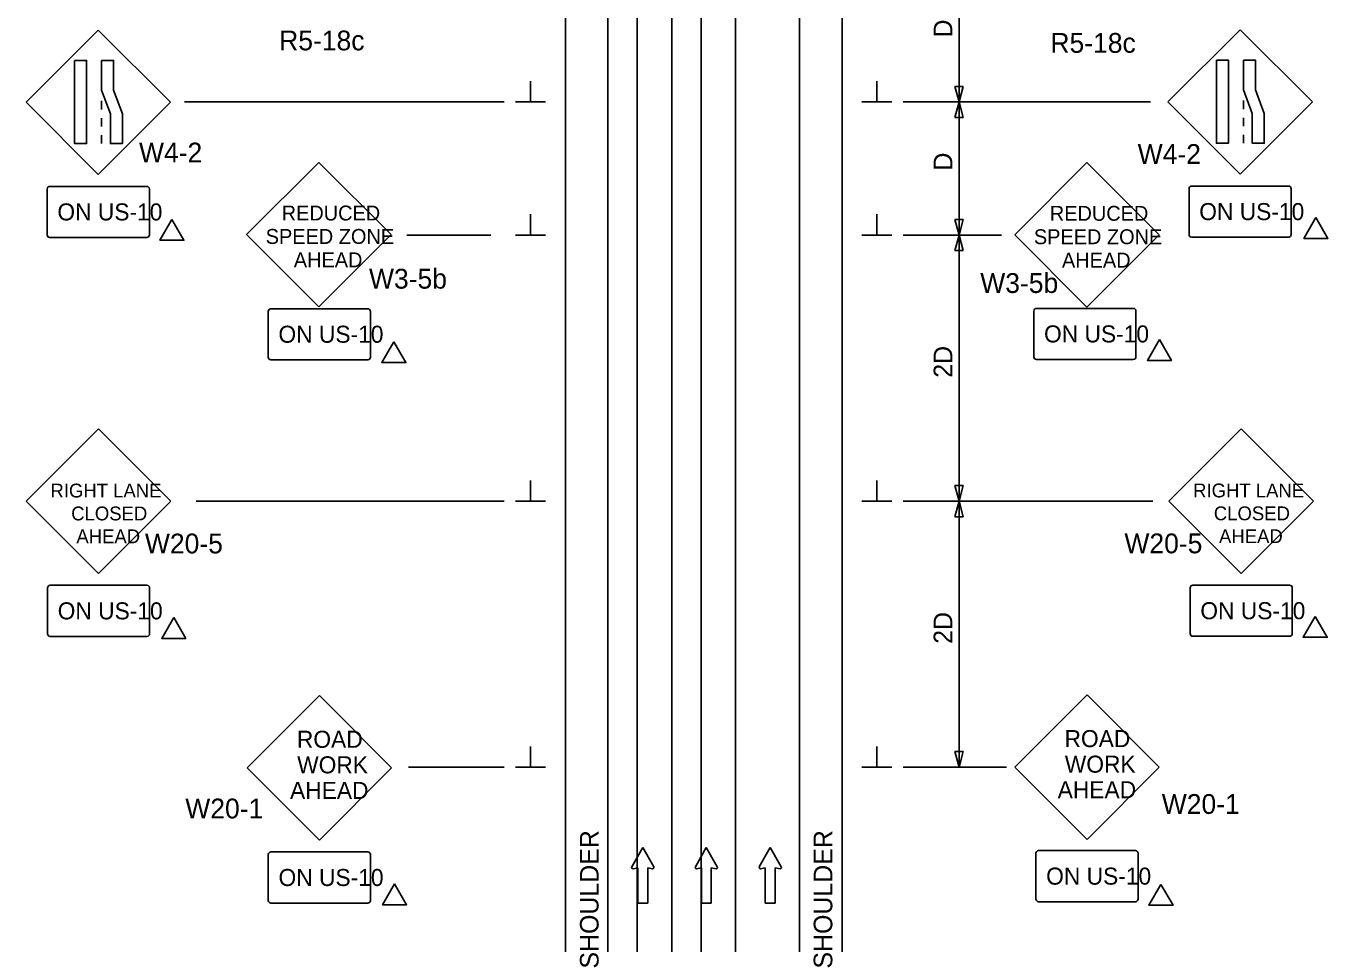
# Model space of a CAD drawing. Extents: x 16303 to 18479, y 5704 to 6974.
# Drawn here: x 16750.9 to 17240.3, y 6152.9 to 6497.9 of the extents above; entities that cross this region are included whole.
import ezdxf

# ---------------------------------------------------------------- set-up
doc = ezdxf.new("R2010")
doc.units = 0
for name, color, linetype in [('ALI_LEGAL_EX', 7, 'Continuous'), ('MT_SCRATCH_LEVEL_E', 7, 'Continuous'), ('PAVT_EDGE_EX', 7, 'Continuous'), ('TRAFFIC_SIGNS_PR', 7, 'Continuous'), ('TYPICAL_TEXT_DIMEN_PR', 7, 'Continuous')]:
    doc.layers.add(name, color=color, linetype=linetype)

msp = doc.modelspace()

# ---------------------------------------------------------------- linework, layer by layer
at = {"layer": 'ALI_LEGAL_EX'}
for p, q in [((16980.68, 6974.12), (16980.68, 6155.98)), ((17004.68, 6974.12), (17004.68, 6155.98)), ((16980.68, 6877.04), (16980.68, 6013.12)), ((17004.68, 6877.04), (17004.68, 6013.12)), ((16993.65, 6024.8), (16993.65, 6525.15)), ((17017.65, 6024.8), (17017.65, 6525.15))]:
    msp.add_line(p, q, dxfattribs=at)
for points in [[(16993.65, 6424.8), (16993.65, 6449.8)], [(17017.65, 6424.8), (17017.65, 6449.8)], [(16993.65, 6324.8), (16993.65, 6349.8)], [(17017.65, 6324.8), (17017.65, 6349.8)], [(16993.65, 6224.8), (16993.65, 6249.8)], [(17017.65, 6224.8), (17017.65, 6249.8)]]:
    msp.add_lwpolyline(points, dxfattribs=at)
at = {"layer": 'MT_SCRATCH_LEVEL_E'}
for p, q in [((16982.72, 6189.09), (16978.61, 6181.85)), ((16986.86, 6181.85), (16982.72, 6189.09)), ((17006.62, 6189.09), (17002.51, 6181.85)), ((17010.77, 6181.85), (17006.62, 6189.09)), ((17030.67, 6189.09), (17026.56, 6181.85)), ((17034.82, 6181.85), (17030.67, 6189.09)), ((16979.09, 6181.17), (16980.87, 6181.49)), ((16980.87, 6181.49), (16980.87, 6168.23)), ((16984.61, 6168.23), (16984.61, 6181.49)), ((16984.61, 6181.49), (16986.38, 6181.17)), ((17002.99, 6181.17), (17004.77, 6181.49)), ((17004.77, 6181.49), (17004.77, 6168.23)), ((17008.51, 6168.23), (17008.51, 6181.49)), ((17008.51, 6181.49), (17010.29, 6181.17)), ((17027.05, 6181.17), (17028.82, 6181.49)), ((17028.82, 6181.49), (17028.82, 6168.23)), ((17032.56, 6168.23), (17032.56, 6181.49)), ((17032.56, 6181.49), (17034.34, 6181.17)), ((16980.87, 6168.23), (16984.61, 6168.23)), ((17004.77, 6168.23), (17008.51, 6168.23)), ((17028.82, 6168.23), (17032.56, 6168.23))]:
    msp.add_line(p, q, dxfattribs=at)
for centre, start, end in [((16979.01, 6181.63), 150.4248, 279.9638), ((16986.45, 6181.63), 260.0362, 29.7731), ((17002.92, 6181.63), 150.4248, 279.9638), ((17010.36, 6181.63), 260.0362, 29.7731), ((17026.97, 6181.63), 150.4248, 279.9638), ((17034.41, 6181.63), 260.0362, 29.7731)]:
    msp.add_arc(centre, 0.463, start, end, dxfattribs=at)
at = {"layer": 'PAVT_EDGE_EX'}
for p, q in [((16953.65, 6525.15), (16953.65, 6062.71)), ((16969.65, 6525.15), (16969.65, 6062.71)), ((17041.65, 6525.15), (17041.65, 6062.71)), ((17057.65, 6525.15), (17057.65, 6062.71))]:
    msp.add_line(p, q, dxfattribs=at)
msp.add_arc((17357.65, 6475.15), 300, 180, 180.00000277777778, dxfattribs=at)
at = {"layer": 'TRAFFIC_SIGNS_PR'}
for p, q in [((16778.07, 6496.36), (16750.91, 6469.21)), ((16805.22, 6469.21), (16778.07, 6496.36)), ((17207.29, 6496.48), (17180.14, 6469.33)), ((17234.45, 6469.33), (17207.29, 6496.48)), ((16750.91, 6469.21), (16778.07, 6442.05)), ((16778.07, 6442.05), (16805.22, 6469.21)), ((16779.31, 6469.7), (16779.31, 6466.5)), ((17180.14, 6469.33), (17207.29, 6442.17)), ((17207.29, 6442.17), (17234.45, 6469.33)), ((17208.53, 6469.82), (17208.53, 6466.62)), ((16779.31, 6463.3), (16779.31, 6460.1)), ((17208.53, 6463.42), (17208.53, 6460.22)), ((16779.31, 6456.9), (16779.31, 6453.7)), ((17208.53, 6457.02), (17208.53, 6453.82)), ((16860.96, 6446.63), (16833.8, 6419.48)), ((16888.11, 6419.48), (16860.96, 6446.63)), ((17149.72, 6446.53), (17122.56, 6419.37)), ((17176.87, 6419.37), (17149.72, 6446.53)), ((16758.86, 6436.61), (16758.86, 6419.41)), ((16759.86, 6437.61), (16796.27, 6437.61)), ((16797.27, 6436.61), (16797.27, 6419.41)), ((17188.09, 6436.73), (17188.09, 6419.53)), ((17189.09, 6437.73), (17225.5, 6437.73)), ((17226.5, 6436.73), (17226.5, 6419.53)), ((16759.86, 6418.41), (16796.27, 6418.41)), ((16833.8, 6419.48), (16860.96, 6392.33)), ((16860.96, 6392.33), (16888.11, 6419.48)), ((17122.56, 6419.37), (17149.72, 6392.22)), ((17149.72, 6392.22), (17176.87, 6419.37)), ((17189.09, 6418.53), (17225.5, 6418.53)), ((17130.75, 6391.76), (17167.15, 6391.76)), ((16841.96, 6390.64), (16841.96, 6373.44)), ((16842.96, 6391.64), (16879.36, 6391.64)), ((16880.36, 6390.64), (16880.36, 6373.44)), ((17129.75, 6390.76), (17129.75, 6373.56)), ((17168.15, 6390.76), (17168.15, 6373.56)), ((16842.96, 6372.44), (16879.36, 6372.44)), ((17130.75, 6372.56), (17167.15, 6372.56)), ((16778.18, 6346.44), (16751.02, 6319.29)), ((16805.33, 6319.29), (16778.18, 6346.44)), ((17207.71, 6346.49), (17180.55, 6319.33)), ((17234.87, 6319.33), (17207.71, 6346.49)), ((16751.02, 6319.29), (16778.18, 6292.13)), ((16778.18, 6292.13), (16805.33, 6319.29)), ((17180.55, 6319.33), (17207.71, 6292.17)), ((17207.71, 6292.17), (17234.87, 6319.33)), ((16758.97, 6286.69), (16758.97, 6269.48)), ((16759.97, 6287.69), (16796.38, 6287.69)), ((16797.38, 6286.69), (16797.38, 6269.48)), ((17188.51, 6286.73), (17188.51, 6269.53)), ((17189.51, 6287.73), (17225.91, 6287.73)), ((17226.91, 6286.73), (17226.91, 6269.53)), ((16759.97, 6268.48), (16796.38, 6268.48)), ((17189.51, 6268.53), (17225.91, 6268.53)), ((16861.19, 6246.23), (16834.04, 6219.07)), ((16888.35, 6219.07), (16861.19, 6246.23)), ((17149.75, 6246.48), (17122.59, 6219.33)), ((17176.9, 6219.33), (17149.75, 6246.48)), ((16834.04, 6219.07), (16861.19, 6191.91)), ((16861.19, 6191.91), (16888.35, 6219.07)), ((17122.59, 6219.33), (17149.75, 6192.17)), ((17149.75, 6192.17), (17176.9, 6219.33)), ((16841.99, 6186.47), (16841.99, 6169.27)), ((16842.99, 6187.47), (16879.4, 6187.47)), ((16880.4, 6186.47), (16880.4, 6169.27)), ((17130.55, 6186.98), (17130.55, 6169.77)), ((17131.55, 6187.98), (17167.95, 6187.98)), ((17168.95, 6186.98), (17168.95, 6169.77)), ((16842.99, 6168.27), (16879.4, 6168.27)), ((17131.55, 6168.77), (17167.95, 6168.77))]:
    msp.add_line(p, q, dxfattribs=at)
for points in [[(16769.17, 6484.94), (16769.17, 6453.7), (16773.66, 6453.7), (16773.66, 6484.94)], [(16779.31, 6484.94), (16779.31, 6473.76), (16782.65, 6464.88), (16782.65, 6453.7), (16787.14, 6453.7), (16787.14, 6464.88), (16783.8, 6473.76), (16783.8, 6484.94)], [(17198.4, 6485.06), (17198.4, 6453.82), (17202.89, 6453.82), (17202.89, 6485.06)], [(17208.53, 6485.06), (17208.53, 6473.88), (17211.88, 6465), (17211.88, 6453.82), (17216.37, 6453.82), (17216.37, 6465), (17213.03, 6473.88), (17213.03, 6485.06)]]:
    msp.add_lwpolyline(points, close=True, dxfattribs=at)
for centre, start, end in [((16759.86, 6436.61), 90, 180), ((16796.27, 6436.61), 0, 90), ((17189.09, 6436.73), 90, 180), ((17225.5, 6436.73), 0, 90), ((16759.86, 6419.41), 180, 270), ((16796.27, 6419.41), 270, 0), ((17189.09, 6419.53), 180, 270), ((17225.5, 6419.53), 270, 0), ((17130.75, 6390.76), 90, 180), ((17167.15, 6390.76), 0, 90), ((16842.96, 6390.63), 90, 180), ((16879.36, 6390.63), 0, 90), ((16842.96, 6373.43), 180, 270), ((16879.36, 6373.43), 270, 0), ((17130.75, 6373.56), 180, 270), ((17167.15, 6373.56), 270, 0), ((16759.97, 6286.69), 90, 180), ((16796.38, 6286.69), 0, 90), ((17189.51, 6286.73), 90, 180), ((17225.91, 6286.73), 0, 90), ((16759.97, 6269.48), 180, 270), ((16796.38, 6269.48), 270, 0), ((17189.51, 6269.53), 180, 270), ((17225.91, 6269.53), 270, 0), ((16842.99, 6186.47), 90, 180), ((16879.4, 6186.47), 0, 90), ((17131.55, 6186.98), 90, 180), ((17167.95, 6186.98), 0, 90), ((16842.99, 6169.27), 180, 270), ((16879.4, 6169.27), 270, 0), ((17131.55, 6169.77), 180, 270), ((17167.95, 6169.77), 270, 0)]:
    msp.add_arc(centre, 1, start, end, dxfattribs=at)
at = {"layer": 'TYPICAL_TEXT_DIMEN_PR'}
for p, q in [((17101.65, 6519.33), (17101.65, 6469.33)), ((16940.52, 6469.33), (16940.52, 6477.11)), ((17070.77, 6469.33), (17070.77, 6477.11)), ((17101.65, 6469.33), (17100.08, 6475.19)), ((17100.08, 6475.19), (17101.65, 6475.19)), ((17101.65, 6475.19), (17103.22, 6475.19)), ((17103.22, 6475.19), (17101.65, 6469.33)), ((16930.65, 6469.33), (16810.45, 6469.33)), ((16934.9, 6469.33), (16946.15, 6469.33)), ((17076.4, 6469.33), (17065.15, 6469.33)), ((17080.65, 6469.33), (17173.63, 6469.33)), ((17100.08, 6463.47), (17101.65, 6469.33)), ((17101.65, 6469.33), (17101.65, 6419.33)), ((17101.65, 6469.33), (17103.22, 6463.47)), ((17101.65, 6463.47), (17100.08, 6463.47)), ((17103.22, 6463.47), (17101.65, 6463.47)), ((16940.52, 6419.33), (16940.52, 6427.11)), ((17070.77, 6419.33), (17070.77, 6427.11)), ((17101.65, 6419.33), (17100.08, 6425.19)), ((17100.08, 6425.19), (17101.65, 6425.19)), ((17101.65, 6425.19), (17103.22, 6425.19)), ((17103.22, 6425.19), (17101.65, 6419.33)), ((16894.04, 6419.33), (16925.67, 6419.33)), ((16934.9, 6419.33), (16946.15, 6419.33)), ((17076.4, 6419.33), (17065.15, 6419.33)), ((17080.65, 6419.33), (17117.63, 6419.33)), ((17100.08, 6413.47), (17101.65, 6419.33)), ((17101.65, 6419.33), (17101.65, 6319.33)), ((17101.65, 6419.33), (17103.22, 6413.47)), ((17101.65, 6413.47), (17100.08, 6413.47)), ((17103.22, 6413.47), (17101.65, 6413.47)), ((16940.52, 6319.33), (16940.52, 6327.11)), ((17070.77, 6319.33), (17070.77, 6327.11)), ((17101.65, 6319.33), (17100.08, 6325.19)), ((17100.08, 6325.19), (17101.65, 6325.19)), ((17101.65, 6325.19), (17103.22, 6325.19)), ((17103.22, 6325.19), (17101.65, 6319.33)), ((16930.65, 6319.33), (16814.81, 6319.33)), ((16934.9, 6319.33), (16946.15, 6319.33)), ((17076.4, 6319.33), (17065.15, 6319.33)), ((17080.65, 6319.33), (17174.46, 6319.33)), ((17100.08, 6313.47), (17101.65, 6319.33)), ((17101.65, 6319.33), (17101.65, 6219.33)), ((17101.65, 6319.33), (17103.22, 6313.47)), ((17101.65, 6313.47), (17100.08, 6313.47)), ((17103.22, 6313.47), (17101.65, 6313.47)), ((16940.52, 6219.33), (16940.52, 6227.11)), ((17070.77, 6219.33), (17070.77, 6227.11)), ((17101.65, 6219.33), (17100.08, 6225.19)), ((17100.08, 6225.19), (17101.65, 6225.19)), ((17101.65, 6225.19), (17103.22, 6225.19)), ((17103.22, 6225.19), (17101.65, 6219.33)), ((16930.65, 6219.33), (16894.65, 6219.33)), ((16934.9, 6219.33), (16946.15, 6219.33)), ((17076.4, 6219.33), (17065.15, 6219.33)), ((17080.65, 6219.33), (17119.46, 6219.33))]:
    msp.add_line(p, q, dxfattribs=at)
for points in [[(16805.76, 6425.2), (16801.24, 6417.36), (16810.29, 6417.36)], [(17235.79, 6425.91), (17231.27, 6418.07), (17240.32, 6418.07)], [(16889.18, 6379.22), (16884.65, 6371.38), (16893.71, 6371.38)], [(17176.95, 6380.02), (17172.43, 6372.18), (17181.48, 6372.18)], [(16806.43, 6275.58), (16801.9, 6267.74), (16810.95, 6267.74)], [(17235.51, 6275.99), (17230.98, 6268.15), (17240.03, 6268.15)], [(16889.45, 6175.47), (16884.92, 6167.64), (16893.97, 6167.64)], [(17177.55, 6175.28), (17173.02, 6167.44), (17182.07, 6167.44)]]:
    msp.add_lwpolyline(points, close=True, dxfattribs=at)

# ---------------------------------------------------------------- texts
at = {"layer": 'TRAFFIC_SIGNS_PR'}
for s, height, p in [('R5-18c', 7.44, (16846.07, 6488.73)), ('R5-18c', 7.44, (17135.99, 6487.81)), ('W4-2', 7.44, (16793.38, 6446.62)), ('W4-2', 7.441, (17168.79, 6446.04)), ('ON US-10', 6.401, (16762.7, 6424.81)), ('ON US-10', 6.401, (17191.93, 6424.93)), ('REDUCED', 5.6, (16847.01, 6424.79)), ('REDUCED', 5.6, (17135.77, 6424.68)), ('SPEED ZONE', 5.6, (16841, 6415.99)), ('SPEED ZONE', 5.6, (17129.77, 6415.88)), ('AHEAD', 5.6, (16851.57, 6407.19)), ('AHEAD', 5.6, (17140.33, 6407.08)), ('W3-5b', 7.44, (16879.84, 6399.18)), ('W3-5b', 7.44, (17109.62, 6397.55)), ('ON US-10', 6.4, (16845.8, 6378.84)), ('ON US-10', 6.4, (17133.59, 6378.96)), ('RIGHT LANE', 5.201, (16760.09, 6320.68)), ('RIGHT LANE', 5.201, (17189.63, 6320.73)), ('CLOSED', 5.201, (16767.89, 6312.08)), ('CLOSED', 5.201, (17197.42, 6312.12)), ('AHEAD', 5.201, (16769.83, 6303.48)), ('AHEAD', 5.201, (17199.37, 6303.52)), ('W20-5', 7.441, (16795.61, 6299.67)), ('W20-5', 7.441, (17163.81, 6299.71)), ('ON US-10', 6.401, (16762.81, 6274.88)), ('ON US-10', 6.401, (17192.34, 6274.93)), ('ROAD', 6.401, (16852.73, 6226.61)), ('ROAD', 6.401, (17141.29, 6226.86)), ('WORK', 6.401, (16852.84, 6217.01)), ('WORK', 6.401, (17141.4, 6217.26)), ('AHEAD', 6.401, (16850.15, 6207.4)), ('AHEAD', 6.401, (17138.71, 6207.66)), ('W20-1', 7.441, (16810.78, 6200.08)), ('W20-1', 7.441, (17177.85, 6201.76)), ('ON US-10', 6.401, (17134.38, 6175.18)), ('ON US-10', 6.401, (16845.83, 6174.67))]:
    msp.add_text(s, height=height, dxfattribs=at).set_placement(p)
at = {"layer": 'TYPICAL_TEXT_DIMEN_PR'}
for s, p in [('D', (17099.09, 6493.55)), ('D', (17099.09, 6443.55)), ('2D', (17099.09, 6365.69)), ('2D', (17099.09, 6265.69)), ('SHOULDER', (16966.14, 6143.64)), ('SHOULDER', (17054, 6143.64))]:
    msp.add_text(s, height=7, rotation=90, dxfattribs=at).set_placement(p)

doc.saveas('drawing.dxf')
